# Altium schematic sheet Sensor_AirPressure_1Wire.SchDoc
size A4; Organization: Altium Limited; Address1: L3, 12a Rodborough Rd; Address2: Frenchs Forest; Address3: NSW; Address4: Australia 2086
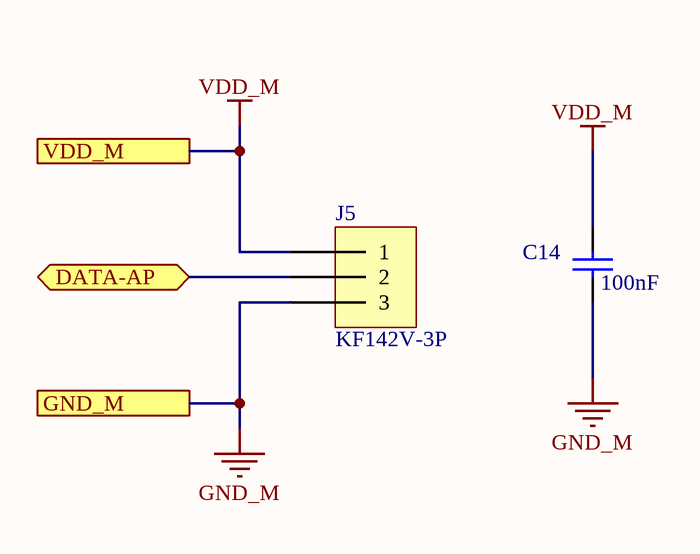
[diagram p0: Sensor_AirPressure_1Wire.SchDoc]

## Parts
C14  100nF  [CAPC1608X87N]
J5  KF142V-3P  [CON KF142V-3P-5.08]

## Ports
DATA-AP (bidir), GND_M, VDD_M

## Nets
GND_M: C14.1 J5.3 ; port GND_M
VDD_M: C14.2 J5.1 ; port VDD_M
DATA-AP: J5.2 ; port DATA-AP

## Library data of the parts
C14 = CC0603_100NF_50V_10%_X7R: Non-polarised capacitor; Part Description: SMD Multilayer Chip Ceramic Capacitor; Manufacturer: GENERIC; Manufacturer1 Part Number: 223858615649; Voltage: 50V; TC: X7R; Tolerance: ±10%; Table: Capacitors SMD
J5 = CON KF142V-3P-5.08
